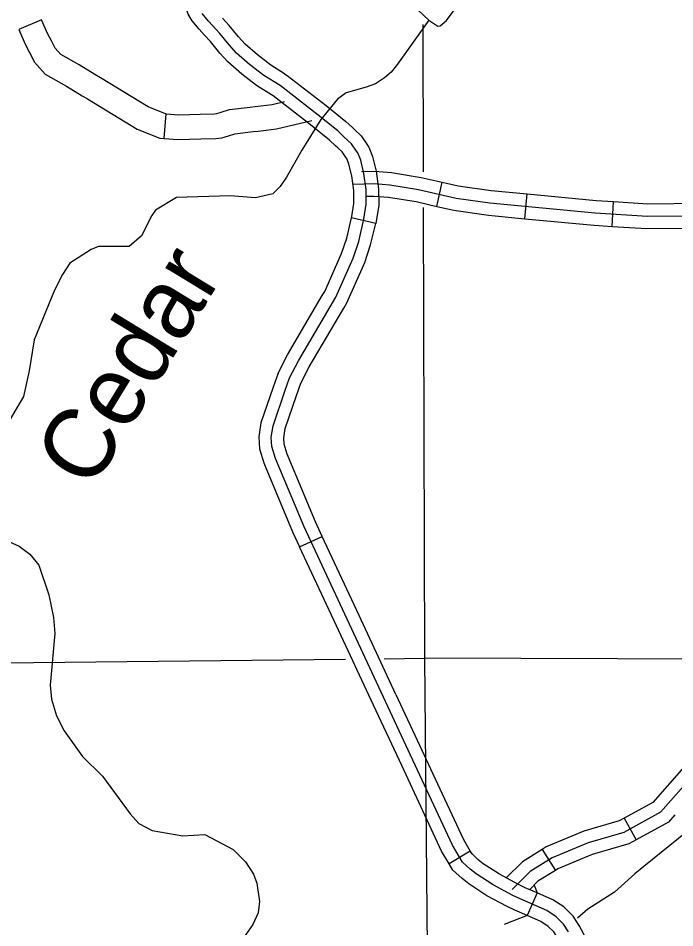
# Model space of a CAD drawing. Extents: x 1373862 to 1376999, y 1168398 to 1170455.
# Drawn here: x 1375410.3 to 1375489.7, y 1168655.8 to 1168765.8 of the extents above; entities that cross this region are included whole.
import ezdxf

# ---------------------------------------------------------------- set-up
doc = ezdxf.new("R2010")
doc.units = 0
for name, color, linetype in [('Level 31', 7, 'Continuous'), ('Level 32', 7, 'Continuous'), ('Level 35', 7, 'Continuous'), ('Level 38', 7, 'Continuous'), ('Level 5', 7, 'Continuous')]:
    doc.layers.add(name, color=color, linetype=linetype)

msp = doc.modelspace()

# ---------------------------------------------------------------- linework, layer by layer
at = {"layer": 'Level 31'}
for p, q in [((1375413.14, 1168765.66), (1375410.39, 1168764.47)), ((1375427.95, 1168751.3), (1375428.19, 1168754.29)), ((1375453.54, 1168741.02), (1375450.62, 1168741.71)), ((1375444.34, 1168701.89), (1375447.06, 1168703.16)), ((1375464.98, 1168665.1), (1375462.41, 1168663.55)), ((1375473.06, 1168660.03), (1375471.85, 1168657.29))]:
    msp.add_line(p, q, dxfattribs=at)
for points in [[(1375432.81, 1168763.82), (1375432.2, 1168764.5), (1375431.35, 1168765.53), (1375430.86, 1168766.31), (1375430.51, 1168767.41), (1375430.35, 1168768.51), (1375430.16, 1168769.65), (1375430.07, 1168774.7)], [(1375450.82, 1168736.82), (1375451.48, 1168738.82), (1375452.12, 1168741.55), (1375452.4, 1168743.33), (1375452.38, 1168745.1), (1375452.12, 1168747.04), (1375451.73, 1168748.65), (1375451.37, 1168749.55), (1375451.23, 1168749.76), (1375450.63, 1168750.64), (1375449.7, 1168751.51), (1375448.94, 1168752.22), (1375446.6, 1168754.12), (1375441.98, 1168757.68), (1375439.99, 1168758.91), (1375438.29, 1168760.24), (1375436.7, 1168761.63), (1375435.82, 1168762.6), (1375434.69, 1168763.99), (1375433.33, 1168765.48), (1375432.57, 1168766.41)], [(1375419.59, 1168759.03), (1375417.68, 1168760.19), (1375415.47, 1168761.44), (1375414.78, 1168762.23), (1375414.34, 1168763.1), (1375413.86, 1168763.99), (1375413.14, 1168765.66)], [(1375442.52, 1168759.11), (1375440.85, 1168760.14), (1375439.25, 1168761.4), (1375437.75, 1168762.7), (1375436.96, 1168763.58), (1375435.83, 1168764.97), (1375435.03, 1168765.84)], [(1375410.39, 1168764.47), (1375411.16, 1168762.68), (1375411.68, 1168761.71), (1375412.28, 1168760.54), (1375413.55, 1168759.08), (1375416.16, 1168757.6), (1375418.03, 1168756.47)], [(1375440.94, 1168756.56), (1375439.13, 1168757.68), (1375437.33, 1168759.09), (1375435.65, 1168760.56), (1375434.69, 1168761.62), (1375433.55, 1168763.01), (1375432.81, 1168763.82)], [(1375428.19, 1168754.29), (1375428.12, 1168754.29), (1375426.03, 1168755.12), (1375420.24, 1168758.63), (1375419.59, 1168759.03)], [(1375442.52, 1168759.11), (1375442.84, 1168758.91), (1375447.53, 1168755.3), (1375449.93, 1168753.35), (1375450.73, 1168752.61), (1375451.01, 1168752.35)], [(1375418.03, 1168756.47), (1375418.68, 1168756.07), (1375424.69, 1168752.43), (1375427.43, 1168751.34), (1375427.95, 1168751.3)], [(1375448.96, 1168750.16), (1375448.68, 1168750.42), (1375447.96, 1168751.08), (1375445.67, 1168752.95), (1375441.13, 1168756.44), (1375440.94, 1168756.56)], [(1375438.35, 1168755.09), (1375438.95, 1168755.17), (1375441.02, 1168755.42), (1375442.52, 1168755.78)], [(1375428.19, 1168754.29), (1375429.73, 1168754.17), (1375432.31, 1168754.25), (1375434.03, 1168754.28), (1375434.34, 1168754.31), (1375434.85, 1168754.47), (1375435.87, 1168754.79), (1375438.35, 1168755.09)], [(1375438.71, 1168752.12), (1375439.31, 1168752.19), (1375441.56, 1168752.47), (1375445.81, 1168753.48)], [(1375427.95, 1168751.3), (1375429.66, 1168751.16), (1375432.38, 1168751.25), (1375434.2, 1168751.28), (1375434.94, 1168751.35), (1375435.75, 1168751.6), (1375436.52, 1168751.85), (1375438.71, 1168752.12)], [(1375451.01, 1168752.35), (1375451.78, 1168751.62), (1375452.48, 1168750.59), (1375452.71, 1168750.24), (1375453.16, 1168749.11), (1375453.6, 1168747.32), (1375453.87, 1168745.21), (1375453.91, 1168743.22), (1375453.6, 1168741.26), (1375453.54, 1168741.02)], [(1375450.62, 1168741.71), (1375450.65, 1168741.84), (1375450.9, 1168743.43), (1375450.88, 1168744.99), (1375450.65, 1168746.77), (1375450.3, 1168748.19), (1375450.03, 1168748.85), (1375449.98, 1168748.93), (1375449.48, 1168749.66), (1375448.96, 1168750.16)], [(1375447.08, 1168732.28), (1375447.38, 1168732.79), (1375449.42, 1168737.36), (1375450.03, 1168739.23), (1375450.62, 1168741.71)], [(1375449.67, 1168730.75), (1375450.06, 1168731.41), (1375452.22, 1168736.28), (1375452.92, 1168738.42), (1375453.54, 1168741.02)], [(1375471, 1168659.3), (1375470.12, 1168659.72), (1375467.73, 1168660.99), (1375465.68, 1168662.34), (1375464.95, 1168662.9), (1375464.05, 1168663.74), (1375462.81, 1168665.8), (1375457.76, 1168676.68), (1375444.87, 1168704.31), (1375441.43, 1168712.58), (1375440.98, 1168714.02), (1375440.9, 1168715.14), (1375441.13, 1168716.55), (1375442.53, 1168720.71), (1375443.12, 1168722.32), (1375444.19, 1168724.4), (1375448.72, 1168732.1), (1375450.82, 1168736.82)], [(1375441.75, 1168722.92), (1375442.88, 1168725.12), (1375447.08, 1168732.28)], [(1375444.5, 1168721.71), (1375445.51, 1168723.68), (1375449.67, 1168730.75)], [(1375441.75, 1168722.92), (1375441.12, 1168721.21), (1375439.66, 1168716.91), (1375439.39, 1168715.21), (1375439.5, 1168713.73), (1375440.02, 1168712.07), (1375440.19, 1168711.67)], [(1375442.96, 1168712.82), (1375442.85, 1168713.09), (1375442.47, 1168714.3), (1375442.41, 1168715.08), (1375442.59, 1168716.19), (1375443.95, 1168720.22), (1375444.5, 1168721.71)], [(1375447.06, 1168703.16), (1375446.24, 1168704.91), (1375442.96, 1168712.82)], [(1375440.19, 1168711.67), (1375443.49, 1168703.7), (1375444.34, 1168701.89)], [(1375451.52, 1168693.59), (1375447.06, 1168703.16)], [(1375448.8, 1168692.32), (1375444.34, 1168701.89)], [(1375455.99, 1168684.02), (1375451.52, 1168693.59)], [(1375453.27, 1168682.76), (1375448.8, 1168692.32)], [(1375455.99, 1168684.02), (1375459.12, 1168677.31), (1375460.45, 1168674.45)], [(1375457.73, 1168673.19), (1375456.4, 1168676.04), (1375453.27, 1168682.76)], [(1375460.45, 1168674.45), (1375464.14, 1168666.5), (1375464.98, 1168665.1)], [(1375462.41, 1168663.55), (1375461.48, 1168665.09), (1375457.73, 1168673.19)], [(1375473.06, 1168660.03), (1375471.62, 1168660.66), (1375470.8, 1168661.06), (1375468.5, 1168662.28), (1375466.55, 1168663.56), (1375465.92, 1168664.04), (1375465.23, 1168664.7), (1375464.98, 1168665.1)], [(1375471.85, 1168657.29), (1375470.37, 1168657.94), (1375469.45, 1168658.38), (1375466.97, 1168659.69), (1375464.81, 1168661.12), (1375463.98, 1168661.76), (1375462.87, 1168662.79), (1375462.41, 1168663.55)], [(1375480.04, 1168651.19), (1375479.73, 1168652.22), (1375479.33, 1168653.47), (1375478.72, 1168655.03), (1375478.15, 1168656.09), (1375477.41, 1168657.21), (1375476.3, 1168658.33), (1375474.94, 1168659.21), (1375473.06, 1168660.03)], [(1375476.86, 1168655.32), (1375476.24, 1168656.26), (1375475.35, 1168657.15), (1375474.23, 1168657.89), (1375471, 1168659.3)], [(1375477.17, 1168650.32), (1375476.86, 1168651.33), (1375476.5, 1168652.47), (1375475.99, 1168653.77), (1375475.57, 1168654.55), (1375475.07, 1168655.31), (1375474.4, 1168655.98), (1375473.51, 1168656.56), (1375471.85, 1168657.29)]]:
    msp.add_lwpolyline(points, dxfattribs=at)
at = {"layer": 'Level 32'}
for p, q in [((1375460.91, 1168743.08), (1375461.59, 1168746)), ((1375471.56, 1168741.59), (1375471.84, 1168744.58)), ((1375482.12, 1168740.66), (1375482.31, 1168743.66)), ((1375483.59, 1168669.08), (1375485.03, 1168666.45)), ((1375473.67, 1168665.3), (1375475.26, 1168662.75))]:
    msp.add_line(p, q, dxfattribs=at)
for points in [[(1375451.84, 1168747.29), (1375453.43, 1168747.33), (1375455.44, 1168747.17), (1375459.02, 1168746.59), (1375461.59, 1168746)], [(1375450.81, 1168745.76), (1375453.39, 1168745.83), (1375455.26, 1168745.67), (1375458.73, 1168745.12), (1375463.25, 1168744.08), (1375467.34, 1168743.49), (1375480.09, 1168742.29), (1375486.39, 1168741.89), (1375500.21, 1168742.02), (1375520.12, 1168742.32), (1375538.87, 1168742.59)], [(1375461.59, 1168746), (1375463.52, 1168745.55), (1375467.51, 1168744.98), (1375471.84, 1168744.58)], [(1375452.35, 1168744.3), (1375453.34, 1168744.33), (1375455.08, 1168744.18), (1375458.44, 1168743.65), (1375460.91, 1168743.08)], [(1375471.84, 1168744.58), (1375480.2, 1168743.79), (1375482.31, 1168743.66)], [(1375482.31, 1168743.66), (1375486.43, 1168743.39), (1375492.76, 1168743.45)], [(1375460.91, 1168743.08), (1375462.97, 1168742.6), (1375467.16, 1168742), (1375471.56, 1168741.59)], [(1375471.56, 1168741.59), (1375479.97, 1168740.8), (1375482.12, 1168740.66)], [(1375482.12, 1168740.66), (1375486.34, 1168740.39), (1375492.78, 1168740.45)], [(1375490.85, 1168675.34), (1375490.81, 1168675.26), (1375487.03, 1168670.96), (1375483.59, 1168669.08)], [(1375492.03, 1168674.38), (1375487.98, 1168669.78), (1375483.55, 1168667.35), (1375479.22, 1168666.07), (1375474.86, 1168664.27), (1375472.22, 1168662.62), (1375470.05, 1168660.45)], [(1375489.71, 1168669.46), (1375488.94, 1168668.59), (1375485.03, 1168666.45)], [(1375483.59, 1168669.08), (1375482.97, 1168668.75), (1375478.72, 1168667.49), (1375474.17, 1168665.61), (1375473.67, 1168665.3)], [(1375485.03, 1168666.45), (1375484.13, 1168665.96), (1375479.72, 1168664.66), (1375475.55, 1168662.93), (1375475.26, 1168662.75)], [(1375473.67, 1168665.3), (1375471.28, 1168663.8), (1375469.32, 1168661.84)], [(1375475.26, 1168662.75), (1375473.16, 1168661.44), (1375472.13, 1168660.41)]]:
    msp.add_lwpolyline(points, dxfattribs=at)
at = {"layer": 'Level 35'}
for points in [[(1375468.54, 1168783.98), (1375458.12, 1168769.25), (1375457.44, 1168768.4), (1375457.36, 1168768.1), (1375459.95, 1168765.61), (1375461.06, 1168764.87), (1375461.33, 1168764.92), (1375462.08, 1168765.57), (1375466.07, 1168770.98), (1375468.31, 1168773.29), (1375471.75, 1168777.91), (1375474.65, 1168781.31), (1375476.78, 1168784.07)], [(1375459.95, 1168765.61), (1375456.18, 1168760.27), (1375455.42, 1168759.32), (1375454.61, 1168758.61), (1375453.5, 1168757.91), (1375452.37, 1168757.48), (1375449.97, 1168756.82), (1375448.92, 1168756.03), (1375446.89, 1168753.6), (1375444.59, 1168749.89), (1375442.74, 1168746.61), (1375442, 1168745.48), (1375441.08, 1168744.61), (1375439.01, 1168744.12), (1375435.92, 1168744.34), (1375429.44, 1168744.16)], [(1375429.44, 1168744.16), (1375426.92, 1168742.6), (1375426.48, 1168741.97), (1375425.22, 1168739.51), (1375423.73, 1168738.23), (1375420.01, 1168738.21), (1375419.14, 1168737.88), (1375416.54, 1168736.2), (1375415.68, 1168734.84), (1375414.7, 1168732.95), (1375412.25, 1168726.92), (1375411.62, 1168723.18), (1375410.93, 1168720.09), (1375407.86, 1168714.87), (1375406.65, 1168713.02), (1375406.23, 1168712.01), (1375405.59, 1168710.25), (1375404.57, 1168706.84), (1375404.24, 1168703.72)], [(1375408.81, 1168702.69), (1375410.41, 1168701.97), (1375411.73, 1168701.02), (1375412.8, 1168699.68), (1375414.02, 1168696.1), (1375414.59, 1168693.35), (1375414.75, 1168691.41), (1375414.16, 1168685.18), (1375414.34, 1168683.45), (1375414.93, 1168681.46), (1375415.85, 1168679.65), (1375418.08, 1168676.54), (1375420.5, 1168674.17), (1375423.84, 1168669.61), (1375424.91, 1168668.43), (1375426.51, 1168667.59), (1375430.22, 1168666.95)], [(1375492.51, 1168668.39), (1375491.22, 1168667.46), (1375485.97, 1168663.23), (1375484.87, 1168662.32), (1375482.42, 1168660.11), (1375479.2, 1168658.08), (1375477.93, 1168656.98)], [(1375430.22, 1168666.95), (1375432.86, 1168667.11), (1375436.32, 1168665.29), (1375437.79, 1168663.77), (1375438.77, 1168662.28), (1375439.15, 1168661.19), (1375439.5, 1168659), (1375439.34, 1168657.64), (1375438.68, 1168656.21), (1375435.85, 1168652.17)]]:
    msp.add_lwpolyline(points, dxfattribs=at)
at = {"layer": 'Level 38'}
for points in [[(1375472.69, 1168660.97), (1375473.06, 1168660.03)], [(1375471.85, 1168657.29), (1375469.06, 1168656.19)]]:
    msp.add_lwpolyline(points, dxfattribs=at)
at = {"layer": 'Level 5'}
for points in [[(1375459.23, 1168765.07), (1375459.27, 1168747.26)], [(1375459.28, 1168742.94), (1375459.42, 1168688.41)], [(1375366.85, 1168687.4), (1375449.87, 1168688.3)], [(1375454.58, 1168688.35), (1375459.42, 1168688.41)], [(1375459.42, 1168688.41), (1375460.42, 1168583.03)], [(1375494.44, 1168688.3), (1375459.42, 1168688.41)]]:
    msp.add_lwpolyline(points, dxfattribs=at)

# ---------------------------------------------------------------- texts
at = {"layer": 'Level 35'}
msp.add_text('Cedar', height=8.448, rotation=58.5621, dxfattribs=at).set_placement((1375419.14, 1168708.55))

doc.saveas('drawing.dxf')
